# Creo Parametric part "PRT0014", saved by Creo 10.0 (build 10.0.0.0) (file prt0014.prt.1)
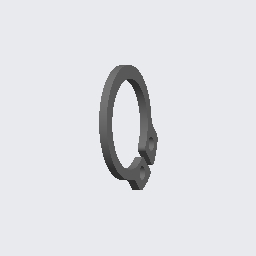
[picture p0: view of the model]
Units: millimeter Newton Second (mmNs); MM, TONNE, SECS

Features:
  1. coordinate system "61741200"
  2. imported feature "Import-ke ID 4"

Other named items: NOTE_0

Notes: 61741200

Surfaces: 16 cylinder, 6 plane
